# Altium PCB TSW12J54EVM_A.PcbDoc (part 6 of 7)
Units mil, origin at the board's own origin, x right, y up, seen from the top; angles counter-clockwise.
Board outline 6301 x 2680 mil, 10 copper layers (Top Layer - L1, Gnd-Plane - L2, Signals - L3, Gnd-Plane - L4, Pwr Plane - L5, Signals - L6, Gnd-Plane - L7, Signals - L8, Gnd-Plane - L9, Bottom Layer - L10), stack 57.8 mil thick; 650 components, 374 nets, 2074 pads, 1402 vias.
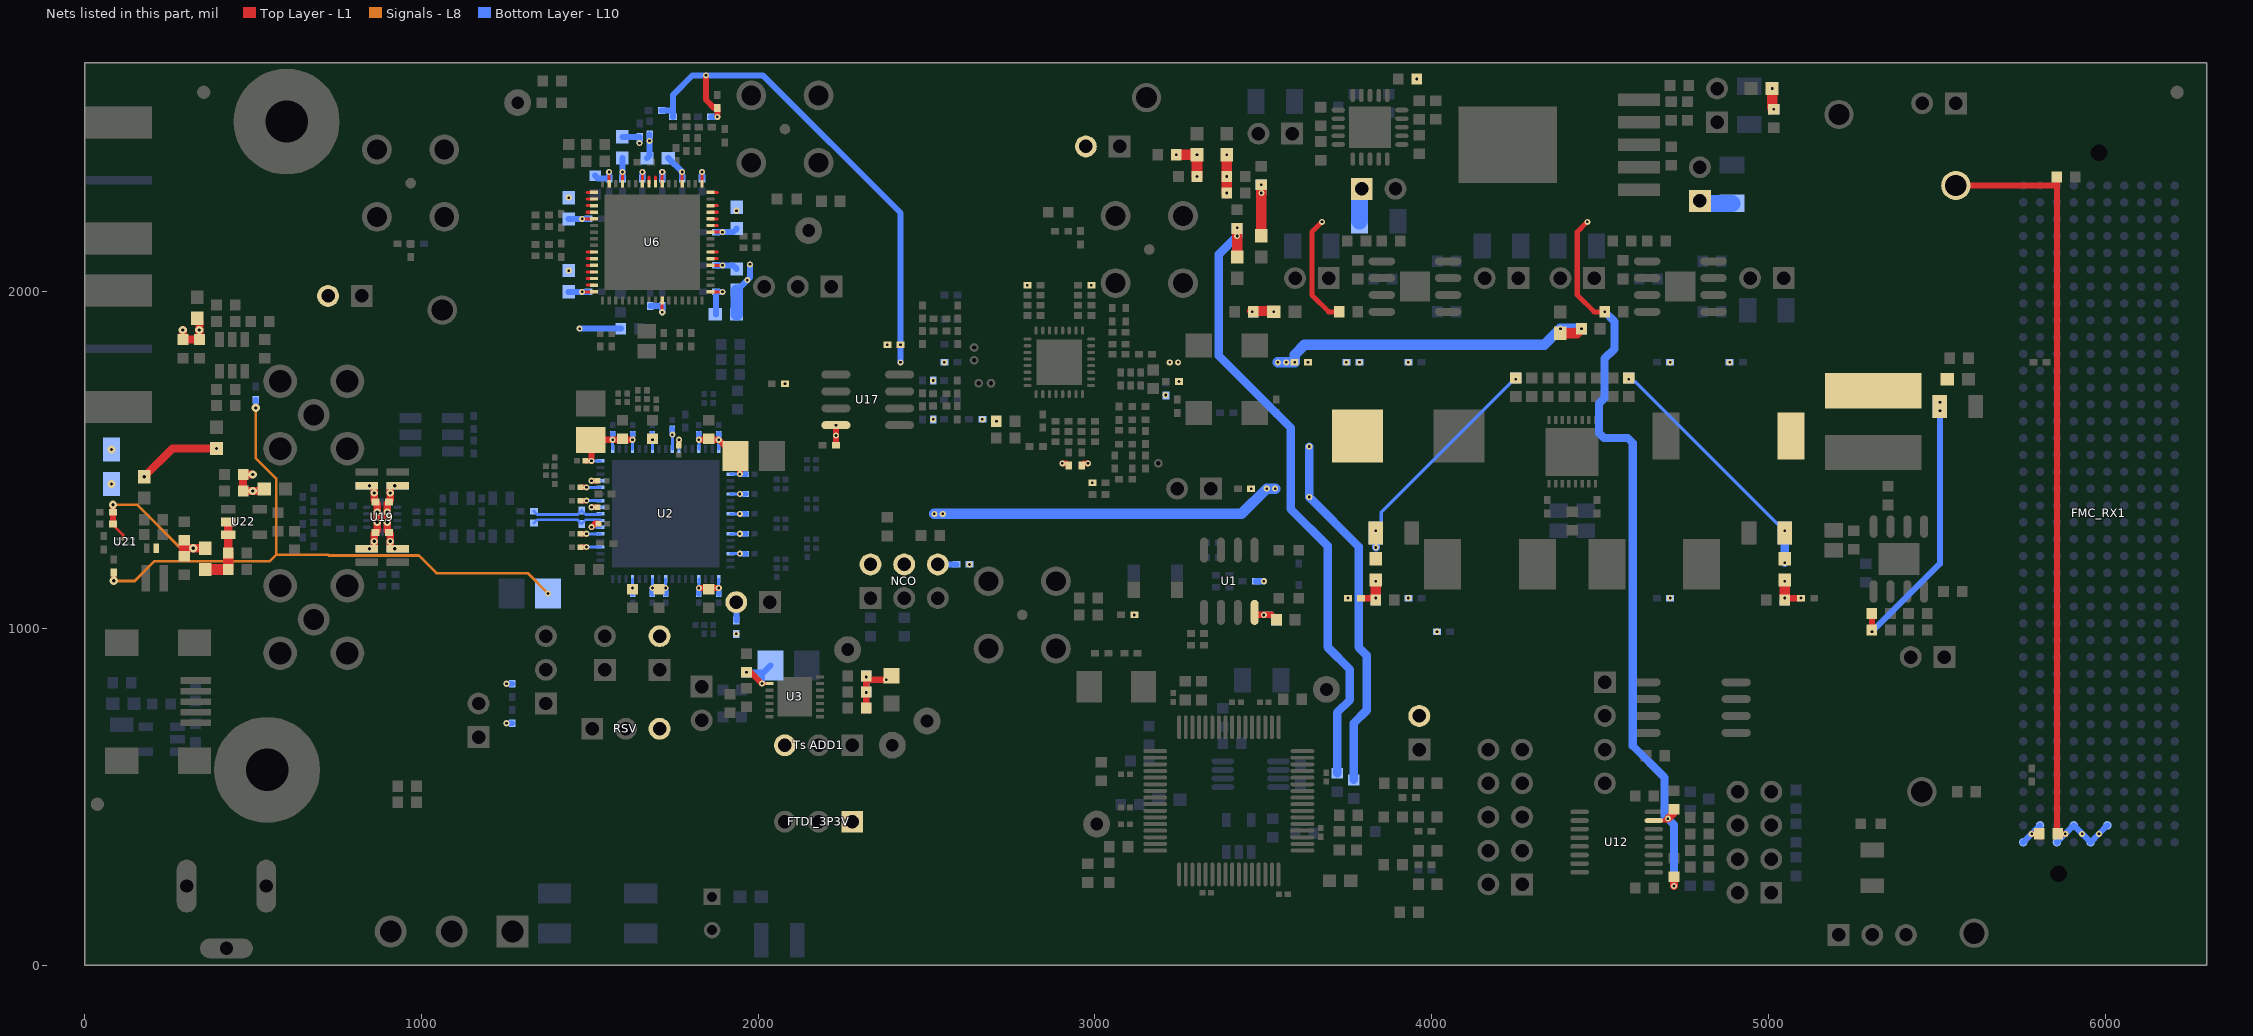
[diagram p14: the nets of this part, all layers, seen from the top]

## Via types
v1: diameter 18, hole 8, Top Layer - L1 to Bottom Layer - L10, tented both sides, 1120 vias
v2: diameter 19.68, hole 7.87, Top Layer - L1 to Bottom Layer - L10, 99 vias
v3: diameter 18, hole 8, Top Layer - L1 to Bottom Layer - L10, tented bottom, 42 vias
v4: diameter 18, hole 8, Top Layer - L1 to Bottom Layer - L10, tented top, 36 vias
v5: diameter 25, hole 10, Top Layer - L1 to Bottom Layer - L10, tented both sides, 32 vias
v6: diameter 21.46, hole 10, Top Layer - L1 to Bottom Layer - L10, tented both sides, 26 vias
v7: diameter 18, hole 8.01, Top Layer - L1 to Bottom Layer - L10, tented both sides, 16 vias
v8: diameter 18, hole 8.01, Top Layer - L1 to Bottom Layer - L10, tented bottom, 16 vias
v9: diameter 25.98, hole 12.99, Top Layer - L1 to Bottom Layer - L10, tented top, 8 vias
v10: diameter 19.68, hole 7.87, Top Layer - L1 to Bottom Layer - L10, tented top, 5 vias
v11: diameter 126, hole 106, Top Layer - L1 to Bottom Layer - L10, tented top, 2 vias

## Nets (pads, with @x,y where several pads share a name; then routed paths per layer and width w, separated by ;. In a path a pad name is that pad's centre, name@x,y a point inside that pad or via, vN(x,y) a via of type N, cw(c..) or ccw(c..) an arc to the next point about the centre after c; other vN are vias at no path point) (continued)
U6-22: U6.22 | length 20.5
  Top Layer - L1 w9: U6.22@1858.79,2097.79 1879.29,2097.79
U6-23: U6.23 | length 20.5
  Top Layer - L1 w9: U6.23@1858.79,2117.47 1879.29,2117.47
U6-27: U6.27 | length 20.5
  Top Layer - L1 w9: U6.27@1858.79,2196.21 1879.29,2196.21
U6-28: U6.28 | length 20.5
  Top Layer - L1 w9: U6.28@1858.79,2215.9 1879.29,2215.9
U6-29: U6.29 | length 20.5
  Top Layer - L1 w9: U6.29@1858.79,2235.58 1879.29,2235.58
U6-30: U6.30 | length 20.5
  Top Layer - L1 w9: U6.30@1858.79,2255.27 1879.29,2255.27
U6-32: U6.32 | length 20.5
  Top Layer - L1 w9: U6.32@1858.79,2294.64 1879.29,2294.64
U6-40: U6.40 | length 20.5
  Top Layer - L1 w9: U6.40@1695.4,2320.23 1695.4,2340.73
U6-41: U6.41 | length 20.5
  Top Layer - L1 w9: U6.41@1675.72,2320.23 1675.72,2340.73
U6-49: U6.49 | length 20.5
  Top Layer - L1 w9: 1491.83,2294.64 U6.49@1512.33,2294.64
U6-50: U6.50 | length 20.5
  Top Layer - L1 w9: 1491.83,2274.95 U6.50@1512.33,2274.95
U6-51: U6.51 | length 20.5
  Top Layer - L1 w9: 1491.83,2255.27 U6.51@1512.33,2255.27
U6-52: U6.52 | length 20.5
  Top Layer - L1 w9: 1491.83,2235.58 U6.52@1512.33,2235.58
U6-58: U6.58 | length 20.5
  Top Layer - L1 w9: 1491.83,2117.47 U6.58@1512.33,2117.47
U6-59: U6.59 | length 20.5
  Top Layer - L1 w9: 1491.83,2097.79 U6.59@1512.33,2097.79
U6-60: U6.60 | length 20.5
  Top Layer - L1 w9: 1491.83,2078.1 U6.60@1512.33,2078.1
U6-61: U6.61 | length 20.5
  Top Layer - L1 w9: 1491.83,2058.42 U6.61@1512.33,2058.42
U6-62: U6.62 | length 20.5
  Top Layer - L1 w9: 1491.83,2038.73 U6.62@1512.33,2038.73
U6-63: U6.63 | length 20.5
  Top Layer - L1 w9: 1491.83,2019.05 U6.63@1512.33,2019.05
VADJ_RX: FMC_RX1.E39 FMC_RX1.F40 FMC_RX1.G39 FMC_RX1.H40 RR6.2 RR7.1 VADJ_RX.1 | length 2487.1
  Top Layer - L1 w18: VADJ_RX.1@5556,2315 5856,2315 ; RR6.2@5856,2340 5856,2315 ; v1(5881,390) 5856,390 5856,2315
  Bottom Layer - L10 w18: FMC_RX1.H40@5856,365 v1(5881,390) FMC_RX1.G39@5906,415 v3(5931,390) FMC_RX1.F40@5956,365 v3(5981,390) FMC_RX1.E39@6006,415
VCC2: C103.1 L2.2 U6.17 | length 120.8
  Top Layer - L1 w9: U6.17@1858.79,1999.36 v1(1893.87,1999.36)
  Bottom Layer - L10 w18: L2.2@1875,1932.5 C103.1@1875,1999.36 v1(1893.87,1999.36)
VCC3: C106.1 L4.2 U6.21 | length 100.4
  Top Layer - L1 w9: U6.21@1858.79,2078.1 v1(1893.87,2078.1)
  Bottom Layer - L10 w18: C106.1@1875,2078.1 v1(1893.87,2078.1) 1925.23,2078.1 L4.2@1935.92,2067.42
VCC4: C111.1 L19.2 U6.26 | length 100.4
  Top Layer - L1 w9: U6.26@1858.79,2176.53 v1(1893.87,2176.53)
  Bottom Layer - L10 w18: C111.1@1875,2176.53 v1(1893.87,2176.53) 1925.23,2176.53 L19.2@1935.92,2187.21
VCC6: C105.1 L3.2 U6.36 | length 112.2
  Top Layer - L1 w9: U6.36@1774.14,2320.23 v1(1774.14,2355.31)
  Bottom Layer - L10 w18: L3.2@1732.95,2396.5 v1(1774.14,2355.31) C105.1@1774.14,2336.45
VCC9: C110.1 L5.2 U6.45 | length 95.1
  Top Layer - L1 w9: U6.45@1596.98,2320.23 v1(1596.98,2355.31)
  Bottom Layer - L10 w18: C110.1@1596.98,2336.45 v1(1596.98,2355.31) L5.2@1596.98,2396.5
VCC11: C120.1 L21.2 U6.53 | length 93.7
  Top Layer - L1 w9: v1(1477.24,2215.9) U6.53@1512.33,2215.9
  Bottom Layer - L10 w18: L21.2@1437.5,2215.9 v1(1477.24,2215.9) C120.1@1496.11,2215.9
VCC12: C121.1 L22.2 U6.64 | length 93.7
  Top Layer - L1 w9: v1(1477.24,1999.36) U6.64@1512.33,1999.36
  Bottom Layer - L10 w18: L22.2@1437.5,1999.36 v1(1477.24,1999.36) C121.1@1496.11,1999.36
VIN_N: R180.2 R181.1 U2.9 | length 212.5
  Bottom Layer - L10 w8: R180.2@1334.32,1347.47 1343.63,1338.16 1464.31,1338.16 R181.1@1476,1349.84 1487.68,1338.16 1530.63,1338.16 U2.9@1532.47,1340
VIN_P: R179.2 R181.2 U2.8 | length 212.5
  Bottom Layer - L10 w8: R179.2@1334.32,1312.84 1343.63,1322.16 1464.32,1322.16 R181.2@1476,1310.47 1487.69,1322.16 1530.63,1322.16 U2.8@1532.47,1320.31
VIO_1P2VA: C39.1 C40.1 C41.2 C42.2 C43.2 C44.2 C45.2 C46.2 C47.2 C48.1 C177.1 C188.1 L15.2 U2.6 U2.11 U2.14 U2.17 U2.18 U2.21 U2.65 VA12.2 | length 654.1
  Top Layer - L1 w16: C41.2@1472.64,1280.94 v1(1490.26,1280.94) ; C42.2@1472.64,1379.37 v1(1490.26,1379.37) ; C44.2@1487.64,1497.48 v1(1505.26,1497.48) ; v1(1505.26,1438.43) C43.2@1522.88,1438.43
  Top Layer - L1 w18: v1(1505.26,1497.48) 1505.26,1560.13 v1(1567.91,1560.13) v1(1626.96,1560.13)
  Top Layer - L1 w31.5: v1(3241.56,2406.01) v1(3303,2406.01) v1(3303,2341.5)
  Bottom Layer - L10 w9: v1(1490.26,1280.94) U2.6@1532.47,1280.94 ; v1(1490.26,1379.37) U2.11@1532.47,1379.37 ; v1(1505.26,1438.43) U2.14@1532.47,1438.43 ; v1(1505.26,1497.48) U2.17@1532.47,1497.48 ; U2.18@1567.91,1532.91 v1(1567.91,1560.13) ; v1(1626.96,1119.87) U2.65@1626.96,1147.09 ; U2.21@1626.96,1532.91 v1(1626.96,1560.13)
  Bottom Layer - L10 w16: v1(1567.91,1560.13) C45.2@1567.91,1577.75 ; C47.2@1626.96,1102.25 v1(1626.96,1119.87) ; v1(1626.96,1560.13) C46.2@1626.96,1577.75
VIO_1P2VD: C60.1 C61.1 C62.2 C63.2 C64.2 C65.2 C66.2 C67.2 C68.2 C69.2 C70.2 C71.2 C72.1 C95.2 C96.2 C189.1 C197.1 L16.2 NCO.2 NCO.4 NCO.6 RSV.3 U2.28 U2.31 U2.34 U2.37 U2.40 U2.43 U2.46 U2.49 U2.52 U2.55 VD12.2 | length 917.5
  Top Layer - L1 w16: C71.2@1764.76,1542.5 v1(1764.76,1560.13)
  Top Layer - L1 w18: v1(1823.81,1119.87) v1(1882.87,1119.87) ; v1(1823.81,1560.13) v1(1882.87,1560.13) 1930.25,1512.74 1930.25,1511.4 1945.51,1496.14 v1(1945.51,1458.11)
  Top Layer - L1 w31.5: v1(3391,2292.5) v1(3391,2406.01)
  Bottom Layer - L10 w9: U2.28@1764.76,1532.91 v1(1764.76,1560.13) ; v1(1823.81,1119.87) U2.55@1823.81,1147.09 ; U2.31@1823.81,1532.91 v1(1823.81,1560.13) ; v1(1882.87,1119.87) U2.52@1882.87,1147.09 ; U2.34@1882.87,1532.91 v1(1882.87,1560.13) ; U2.49@1918.3,1221.89 v1(1945.51,1221.89) ; U2.46@1918.3,1280.94 v1(1945.51,1280.94) ; U2.43@1918.3,1340 v1(1945.51,1340) ; U2.40@1918.3,1399.06 v1(1945.51,1399.06) ; U2.37@1918.3,1458.11 v1(1945.51,1458.11)
  Bottom Layer - L10 w16: C62.2@1823.81,1102.25 v1(1823.81,1119.87) ; v1(1823.81,1560.13) C70.2@1823.81,1577.75 ; C63.2@1882.87,1102.25 v1(1882.87,1119.87) ; v1(1882.87,1560.13) C69.2@1882.87,1577.75 ; v1(1945.51,1221.89) C64.2@1963.13,1221.89 ; v1(1945.51,1280.94) C65.2@1963.13,1280.95 ; v1(1945.51,1340) C66.2@1963.13,1340 ; v1(1945.51,1399.06) C67.2@1963.13,1399.05 ; v1(1945.51,1458.11) C68.2@1963.13,1458.11
  Bottom Layer - L10 w18: C96.2@1935,1023.19 VD12.2@1935,1078 ; NCO.6@2533.5,1190 C95.2@2588.31,1190
  other v1: 3391,2341.5
VIO_1P4: 1V2ADC_INT.1 C176.1 C190.1 C219.1 C221.1 C224.1 C225.1 L14.2 R83.1 | length 253.7
  Top Layer - L1 w19.5: C219.1@3790.53,1090 v1(3833.85,1090)
  Top Layer - L1 w31.5: v1(3833.85,1090) L14.2@3833.85,1143.5
  Bottom Layer - L10 w24: C190.1@3833.85,1084 v1@3833.85,1143.5
  Bottom Layer - L10 w51: R83.1@3785.18,2210.56 3785.18,2297.91 1V2ADC_INT.1@3792.27,2305
  other v1: 3930.31,1090 3833.85,1140 3785.68,1790 3930.31,1790
VIO_1P4V: C175.1 C182.1 C183.1 L12.2 L14.1 R82.2 | length 675.5
  Bottom Layer - L10 w10: C183.1@3833.85,1283 3850,1299.15 3850,1344.56 R82.2@4249,1743.56
  Bottom Layer - L10 w24: v1@3833.85,1240 C183.1@3833.85,1283
  other v1: 3833.85,1240 3833.85,1290 4249,1740
VIO_1P9V: C49.1 C50.1 C51.2 C52.2 C53.2 C54.2 C55.2 C56.2 C57.2 C58.2 C59.1 C130.1 C191.1 C202.1 L18.2 R39.1 R71.1 R80.1 R123.2 R170.1 R173.1 U2.4 U2.7 U2.10 U2.13 U2.24 U2.27 U2.60 U2.62 U12.15 VA19.2 | length 4980.1
  Top Layer - L1 w13: U12.15@4659.24,429.5 4695.5,429.5 v1(4701,435)
  Top Layer - L1 w15: v1(3674,2207) 3644,2177 3644,1990 3694,1940 R39.1@3725.44,1940 ; v1(4462,2207) 4432,2177 4432,1990 4482,1940 v1(4513.44,1940)
  Top Layer - L1 w16: v5(86.73,1140.99) R173.1@86.73,1165.3 ; C51.2@1472.64,1241.57 v1(1490.26,1241.57) ; C54.2@1472.64,1418.74 v1(1490.26,1418.74) ; v1(1505.26,1359.68) C53.2@1522.88,1359.68
  Top Layer - L1 w18: v1(1505.26,1300.63) 1515.58,1310.95 C52.2@1525.57,1310.95
  Top Layer - L1 w24: v1(4701,435) 4719,453 C130.1@4719,462.75 ; v1(4719,235.22) R123.2@4719,262.97
  Top Layer - L1 w31.5: v1(5010.5,2602.93) 5010.5,2546.49 v1(5015.5,2541.49)
  Signals - L8 w8: v5@98.73,1140.99 148.99,1140.99 207.5,1199.5 550.22,1199.5 569,1218.28 ; v5(507.99,1654.53) 508.02,1505.98 569,1445 569,1218.28 ; v1(1376,1103.87) 1315.87,1164 1045,1164 992.48,1216.52 724.48,1216.52 722.72,1218.28 569,1218.28
  Bottom Layer - L10 w9: v1(1490.26,1241.57) U2.4@1532.47,1241.57 ; v1(1490.26,1418.74) U2.13@1532.47,1418.74 ; v1(1505.26,1300.63) U2.7@1532.47,1300.63 ; v1(1505.26,1359.68) U2.10@1532.47,1359.68 ; v1(1686.02,1119.87) U2.62@1686.02,1147.09 ; U2.24@1686.02,1532.91 v1(1686.02,1560.13) ; v1(1725.39,1119.87) U2.60@1725.39,1147.09 ; U2.27@1745.07,1532.91 v1(1745.07,1575.13)
  Bottom Layer - L10 w16: v5(507.99,1654.53) R170.1@508.02,1678.84 ; C58.2@1686.01,1102.25 v1(1686.02,1119.87) ; v1(1686.02,1560.13) C55.2@1686.02,1577.75 ; C57.2@1725.39,1102.25 v1(1725.39,1119.87) ; v1(1745.07,1575.13) C56.2@1745.07,1592.75
  Bottom Layer - L10 w24: v1(4513.44,1940) 4542,1911.44 4542,1830 4513,1801 4513,1683.97 4496.61,1667.58 4496.61,1579.64 4511.25,1565 4581.97,1565 4596.61,1550.36 4596.61,651.39 4691,557 4691,445 v1(4701,435) 4719,417 v1(4719,235.22)
  other v1: 3955.22,2631
VIO_2P25: 1V9INT.1 C199.1 C203.1 C222.1 C223.1 C226.1 C227.1 L20.2 R95.1 | length 258.5
  Top Layer - L1 w19.5: v1(5048.15,1090) v1(5096.31,1090)
  Top Layer - L1 w31.5: v1(5048.15,1090) L20.2@5048.15,1143.5
  Bottom Layer - L10 w24: C203.1@5048.15,1084 v1@5048.15,1143.5
  Bottom Layer - L10 w51: 1V9INT.1@4796,2269.07 4803.09,2261.98 R95.1@4890.44,2261.98
  other v1: 4707.69,1090 5048.15,1140 4707.69,1790 4884.32,1790
VIO_2P25V: C174.2 C180.1 C181.1 L11.1 L20.1 R81.1 | length 745.3
  Bottom Layer - L10 w10: R81.1@4585,1743.56 4595.56,1733 4604,1733 5032,1305 5032,1299.15 C181.1@5048.15,1283
  Bottom Layer - L10 w24: v1@5048.15,1195 C181.1@5048.15,1283
  other v1: 5048.15,1195 5048.15,1290 4585,1740
VIO_3P3V: "Ts ADD1.3" C24.1 C25.1 C27.1 C95.1 C96.1 C115.1 C125.1 C153.1 C163.1 C215.1 C216.1 C217.1 C218.1 C219.2 C220.1 C224.2 FTDI_3P3V.1 J3.2 L9.2 R1.2 R14.2 R15.2 R16.2 R31.2 R32.2 TEMP.1 U1.8 U3.2 | length 651.2
  Top Layer - L1 w9: v1(2011.28,836.13) U3.2@2033.47,836.13
  Top Layer - L1 w18: v1(1965.28,869.44) 1977.96,869.44 v1(2011.28,836.13) ; R16.2@2320.84,763.41 v1(2320.84,809.41) 2320.84,847.47 v1(2380.28,847.47)
  Top Layer - L1 w19.5: U1.8@3474,1040 3524.93,1040 C125.1@3538.93,1026
  Top Layer - L1 w30: C153.1@3467,1942.56 3528.45,1942.56 v1(3531.01,1940)
  Bottom Layer - L10 w18: v1(1965.28,869.44) 2016.17,869.44 C27.1@2036.14,889.42 ; v1(2011.28,836.13) C27.1@2011.3,869.44 ; v1(2320.84,809.41) v1(2320.84,855.81) ; v1(3467,1940) v1(3531.01,1940) ; R1.2@3477.69,1140 v1(3501.5,1140)
  Bottom Layer - L10 w19.5: v1(3501.5,1040) 3524.93,1040 C115.1@3538.93,1026
  other v1: 1935,983.82 4015.31,990 3116.68,1040 3751.16,1090 2627.68,1190 2079.68,1726 3632.24,1790 3746.31,1790 2383.32,1842
VIO_3P3V_LMK_CLK: C116.1 C171.1 L2.1 L4.1 L13.2 L19.1 L21.1 L22.1 R47.2 R131.1 | length 2191.3
  Top Layer - L1 w31.5: L13.2@3422,2102.99 C116.1@3422,2187.44
  Bottom Layer - L10 w18: v1(1470,1890) R47.2@1592.23,1890 ; L4.1@1935.92,2001.92 v1(1968,2034) 1976,2042 v1(1976,2081)
  Bottom Layer - L10 w25: v1(3422,2165) 3368,2111 3368,1809 3581,1596 3581,1355 3691,1245 3691,944 3757,878 3757,788 3719,750 R131.1@3719,569.71
  Bottom Layer - L10 w31.5: v1@3422,2162.44 C171.1@3422,2187.44
  Bottom Layer - L10 w37.5: L2.1@1935.92,1932.5 L4.1@1935.92,2001.92
  other v1: 1437.5,2062.35 3422,2190 1935.92,2240 1437.5,2278.89
VIO_3P3V_LMK_PLL: C102.1 C104.1 C107.1 C108.1 C109.1 C164.1 C165.1 C206.1 C207.1 C208.1 C209.1 L3.1 L5.1 L10.2 U6.10 U6.33 U6.39 U6.42 U6.47 | length 669.2
  Top Layer - L1 w9: U6.47@1557.61,2320.23 v1(1557.61,2355.31) ; U6.42@1656.03,2320.23 v1(1656.03,2355.31) ; v1(1715.09,1938.69) U6.10@1715.09,1973.77 ; U6.39@1715.09,2320.23 v1(1715.09,2355.31) ; U6.33@1833.2,2320.23 v1(1833.2,2355.31)
  Top Layer - L1 w31.5: L10.2@3494,2165.99 v1(3494,2317.5)
  Bottom Layer - L10 w18: C108.1@1515.92,2344.32 1523.79,2336.44 C209.1@1557.61,2336.45 v1(1557.61,2355.31) ; L5.1@1596.98,2459.5 C107.1@1647.92,2459.5 v1(1647.92,2440.63) ; C208.1@1656.03,2336.45 v1(1656.03,2355.31) ; L3.1@1669.96,2396.5 1677.05,2403.59 v1(1677.05,2447.5) C104.1@1677.05,2466.37 ; C109.1@1679.72,1957.55 C102.1@1715.09,1957.55 v1(1715.09,1938.69) ; C207.1@1715.09,2336.45 v1(1715.09,2355.31) ; C206.1@1833.2,2336.45 v1(1833.2,2355.31)
  Bottom Layer - L10 w31.5: v1(3494,2292.5) v1(3494,2317.5)
VIO_3P3V_LMX: C144.1 C152.1 C216.2 C217.2 C258.2 C259.2 C260.2 L1.1 L6.2 L27.1 L28.1 L29.1 L30.1 L31.1 L32.1 L33.1 L34.1 R130.1 R146.1 R151.1 R156.2 R157.2 R163.2 R164.2 U17.8 | length 3776.2
  Top Layer - L1 w18: v1(1845,2642) 1845,2569.78 1869.91,2544.87 C259.2@1878.91,2544.87 v1(1878.91,2519) ; C258.2@2230.84,1544.09 v1(2230.84,1603.5) ; v1(2903.08,1490) 2914.92,1490 L30.1@2921.92,1483 ; L29.1@2960.55,1483 2967.55,1490 v1(2979.39,1490)
  Top Layer - L1 w31.5: L6.2@4382,1876.5 4430.94,1876.5 v1(4444.44,1890)
  Bottom Layer - L10 w18: C260.2@1713.69,2537.87 1747.3,2537.87 ; R157.2@1747.3,2519 1747.3,2537.87 ; R156.2@1860.04,2519 v1(1878.91,2519) ; v1(2422.69,1790) 2422.69,2233.31 2014,2642 1805,2642 1747.3,2584.3 1747.3,2537.87
  Bottom Layer - L10 w25: v1(3636.2,1540) v1(3636.2,1390) 3783,1243.2 3783,944 3807,920 3807,757 3768,718 R130.1@3768,550.02
  Bottom Layer - L10 w31.5: v1(3542.87,1790) v1(3592.87,1790) 3592.87,1812.87 3622,1842 4334,1842 v1(4382,1890) v1(4444.44,1890)
  other v1: 3463.69,1415 2992.31,1432.5 2230.84,1572.81 2707.44,1615 2519.36,1620.81 2665.69,1620.82 3210,1692.98 3249.52,1733.13 2519.36,1736.19 2552.68,1790 3221.92,1790 3246.92,1790 3567.87,1790 2422.69,1842 2799.35,2019.09 2989.12,2019.09
VIO_3P75: "LMH PD.2" C265.1 C267.2 C269.2 C271.1 C273.1 C274.1 C275.1 C280.1 C281.1 L43.2 R183.1 U19.1 U19.10 | length 638.3
  Top Layer - L1 w19.68: C265.1@907.26,1237.02 C265.1@930.03,1237.02 ; C271.1@907.26,1423.29 C271.1@930.03,1423.29
  Top Layer - L1 w21.46: C265.1@907.26,1237.02 v6(907.26,1258.4) 907.26,1280.91 898.34,1289.83 v6(898.34,1315.42) v6(898.34,1344.89) 898.34,1370.48 907.26,1379.4 v6(907.26,1401.91) C271.1@907.26,1423.29
  Top Layer - L1 w24: v5(291.99,1886.02) C280.1@291.99,1857.77 C281.1@340.99,1857.77 v5(340.99,1886.02) 340.99,1914.51 L43.2@335,1920.5
  Bottom Layer - L10 w9.84: v6(898.34,1315.42) 903.3,1310.74 903.3,1262.37 v6(907.26,1258.4) ; v6(898.34,1344.89) 903.3,1349.57 U19.10@903.3,1375.43 903.3,1397.94 v6(907.26,1401.91)
  Bottom Layer - L10 w16: v1(1252.51,718.32) R183.1@1269.78,718.32
  Bottom Layer - L10 w19.68: C267.2@907.26,1237.02 C267.2@930.03,1237.02 ; C269.2@907.26,1423.29 C269.2@930.03,1423.29
  Bottom Layer - L10 w21.46: v6(898.34,1315.42) v6(898.34,1344.89) ; C267.2@907.26,1237.02 v6(907.26,1258.4) ; v6(907.26,1401.91) C269.2@907.26,1423.29
  other v5: 80,1531.12
  other v6: 921.26,1236.94 921.26,1423.38
VIO_4P05V: C154.2 C156.2 C157.2 L7.1 L8.2 L35.1 L36.1 R72.1 | length 2081.1
  Top Layer - L1 w18: R72.1@5306.88,995 C154.2@5306.88,1044
  Top Layer - L1 w24: v5(177.17,1450.49) 260.71,1534.03 v5(391.73,1534.03)
  Bottom Layer - L10 w18: v1(5306.88,990) 5508.85,1191.97 v1(5508.85,1646.25)
  Bottom Layer - L10 w31.5: v1(2523,1340) v1(2548,1340) 3435,1340 v1(3510,1415) v1(3535,1415)
  other v1: 5508.85,1671.25
VIO_-1P25: C264.2 C266.1 C268.1 C270.2 C273.2 C274.2 C275.2 C289.1 C290.1 L44.2 R182.1 U19.3 U19.8 | length 638.3
  Top Layer - L1 w19.68: C264.2@837.19,1237.02 C264.2@859.96,1237.02 ; C270.2@837.19,1423.29 C270.2@859.96,1423.29
  Top Layer - L1 w21.46: C264.2@859.96,1237.02 v6(859.96,1258.4) 859.96,1280.91 C273.2@863.93,1284.88 868.88,1289.83 v6(868.88,1315.42) v6(868.88,1344.89) 868.88,1370.48 C274.2@863.93,1375.43 859.96,1379.4 v6(859.96,1401.91) C270.2@859.96,1423.29
  Top Layer - L1 w24: v5(498.81,1457) C290.1@470.56,1457 C289.1@470.56,1408 v5(498.81,1408) 527.3,1408 L44.2@533.3,1413.99
  Bottom Layer - L10 w9.84: v6(859.96,1258.4) 863.93,1262.37 U19.3@863.93,1284.88 863.93,1310.74 v6(868.88,1315.42) ; v6(859.96,1401.91) 863.93,1397.94 U19.8@863.93,1375.43 863.93,1349.57 v6(868.88,1344.89)
  Bottom Layer - L10 w16: v1(1252.51,835.69) R182.1@1269.78,835.68
  Bottom Layer - L10 w19.68: C266.1@837.19,1237.02 C266.1@859.96,1237.02 ; C268.1@837.19,1423.29 C268.1@859.96,1423.29
  Bottom Layer - L10 w21.46: C266.1@859.96,1237.02 v6(859.96,1258.4) ; v6(859.96,1401.91) C268.1@859.96,1423.29 ; v6(868.88,1315.42) v6(868.88,1344.89)
  other v5: 80,1428.76
  other v6: 845.96,1236.94 845.96,1423.38
VIO_-3P25: C287.1 C288.1 L42.2 U22.2 U22.3 | length 209.1
  Top Layer - L1 w25: C288.1@426.07,1224 U22.3@426.07,1278.6 U22.2@426.07,1316
  Top Layer - L1 w31.5: L42.2@358,1175 C287.1@426.07,1175 C288.1@426.07,1224
VIO_-3P25V: C284.2 C285.2 C286.1 D1.2 L42.1 R174.2 U21.B2 | length 515
  Top Layer - L1 w8: R174.2@84.42,1309.99 84.42,1307.3 113.86,1277.86 U21.B2@113.86,1265.86
  Top Layer - L1 w19: R174.2@84.42,1309.99 C286.1@84.42,1344.99 v5(84.42,1367.33)
  Top Layer - L1 w25: 295.73,1237.99 v5(323,1237.99) L42.1@358,1237.99
  Top Layer - L1 w31.5: C284.2@295.73,1214.55 295.73,1237.99 C285.2@295.73,1261.43
  Signals - L8 w8: v5@96.42,1367.33 155.95,1367.33 285.29,1237.99 v5@335,1237.99
VIO_B_M2C_RX: FMC_RX1.J39 FMC_RX1.K40 RR7.2 | length 93.2
  Top Layer - L1 w18: v1(5781,390) RR7.2@5803.44,390
  Bottom Layer - L10 w18: FMC_RX1.K40@5756,365 v1(5781,390) FMC_RX1.J39@5806,415
pads on no net: 5VDC.3 "SH-Ts ADD1_1_2.0" FID1.1 FID2.1 FID3.1 FMC_RX1.401 FMC_RX1.402 FMC_RX1.A22 FMC_RX1.A23 FMC_RX1.A26 FMC_RX1.A27 FMC_RX1.A30 FMC_RX1.A31 FMC_RX1.A34 FMC_RX1.A35 FMC_RX1.A38 FMC_RX1.A39 FMC_RX1.B1 FMC_RX1.B4 FMC_RX1.B5 FMC_RX1.B8 FMC_RX1.B9 FMC_RX1.B20 FMC_RX1.B21 FMC_RX1.B24 FMC_RX1.B25 FMC_RX1.B28 FMC_RX1.B29 FMC_RX1.B32 FMC_RX1.B33 FMC_RX1.B36 FMC_RX1.B37 FMC_RX1.B40 FMC_RX1.C2 FMC_RX1.C3 FMC_RX1.C10 FMC_RX1.C11 FMC_RX1.C14 FMC_RX1.C15 FMC_RX1.C18 FMC_RX1.C19 FMC_RX1.C22 FMC_RX1.C23 FMC_RX1.C26 FMC_RX1.C27 FMC_RX1.D8 FMC_RX1.D9 FMC_RX1.D11 FMC_RX1.D12 FMC_RX1.D14 FMC_RX1.D15 FMC_RX1.D17 FMC_RX1.D18 FMC_RX1.D20 FMC_RX1.D21 FMC_RX1.D23 FMC_RX1.D24 FMC_RX1.D27 FMC_RX1.D29 FMC_RX1.D33 FMC_RX1.D34 FMC_RX1.E2 FMC_RX1.E3 FMC_RX1.E6 FMC_RX1.E7 FMC_RX1.E9 FMC_RX1.E10 FMC_RX1.E15 FMC_RX1.E16 FMC_RX1.E18 FMC_RX1.E19 FMC_RX1.E21 FMC_RX1.E22 FMC_RX1.E24 FMC_RX1.E25 FMC_RX1.E27 FMC_RX1.E28 FMC_RX1.E30 FMC_RX1.E31 FMC_RX1.E33 FMC_RX1.E34 FMC_RX1.E37 FMC_RX1.F4 FMC_RX1.F5 FMC_RX1.F7 FMC_RX1.F8 FMC_RX1.F10 FMC_RX1.F11 FMC_RX1.F13 FMC_RX1.F14 FMC_RX1.F16 FMC_RX1.F17 FMC_RX1.F19 FMC_RX1.F20 FMC_RX1.F22 FMC_RX1.F23 FMC_RX1.F25 FMC_RX1.F26 FMC_RX1.F28 FMC_RX1.F29 FMC_RX1.F31 FMC_RX1.F32 FMC_RX1.F34 FMC_RX1.F35 FMC_RX1.F37 FMC_RX1.F38 FMC_RX1.G2 FMC_RX1.G3 FMC_RX1.G15 FMC_RX1.G16 FMC_RX1.G18 FMC_RX1.G19 FMC_RX1.G21 FMC_RX1.G22 FMC_RX1.G24 FMC_RX1.G25 FMC_RX1.G28 FMC_RX1.G31 FMC_RX1.H1 FMC_RX1.H4 FMC_RX1.H5 FMC_RX1.H7 FMC_RX1.H8 FMC_RX1.H10 FMC_RX1.H11 FMC_RX1.H13 FMC_RX1.H14 FMC_RX1.H16 FMC_RX1.H17 FMC_RX1.H19 FMC_RX1.H20 FMC_RX1.H22 FMC_RX1.H23 FMC_RX1.H25 FMC_RX1.H26 FMC_RX1.H28 FMC_RX1.H29 FMC_RX1.H32 FMC_RX1.H35 FMC_RX1.J2 FMC_RX1.J3 FMC_RX1.J6 FMC_RX1.J7 FMC_RX1.J9 FMC_RX1.J10 FMC_RX1.J12 FMC_RX1.J13 FMC_RX1.J18 FMC_RX1.J19 FMC_RX1.J21 FMC_RX1.J22 FMC_RX1.J24 FMC_RX1.J25 FMC_RX1.J27 FMC_RX1.J28 FMC_RX1.J30 FMC_RX1.J31 FMC_RX1.J33 FMC_RX1.J34 FMC_RX1.J36 FMC_RX1.J37 FMC_RX1.K1 FMC_RX1.K4 FMC_RX1.K5 FMC_RX1.K7 FMC_RX1.K8 FMC_RX1.K10 FMC_RX1.K11 FMC_RX1.K13 FMC_RX1.K14 FMC_RX1.K16 FMC_RX1.K17 FMC_RX1.K19 FMC_RX1.K20 FMC_RX1.K22 FMC_RX1.K23 FMC_RX1.K25 FMC_RX1.K26 FMC_RX1.K31 FMC_RX1.K32 FMC_RX1.K34 FMC_RX1.K35 H3.0 H4.0 H5.1 H6.1 S1.3 SH-1V2ADC_INT_1_2.0 SH-1V2ADC_LDO_1_2.0 SH-1V9ADC_1_2.0 SH-1V9INT_1_2.0 SH-5V_12V_1_2.0 SH-FTDI_3P3V_1_2.0 SH-J2_1_2.0 SH-LMK_INT_1_2.0 SH-LMK_LDO_1_2.0 SH-LMX_INT_1_2.0 SH-LMX_LDO_1_2.0 SH-RSV_1_2.0 U3.1 U3.3 U3.4 U5.2 U5.7 U8.2 U8.7 U10.2 U10.3 U10.4 U10.9 U10.13 U10.14 U10.17 U13.21 U13.22 U13.23 U13.24 U13.30 U13.32 U13.33 U13.34 U13.36 U13.44 U13.45 U13.46 U13.48 U13.52 U13.53 U13.54 U13.55 U13.57 U13.58 U13.59 U13.60 U15.6 U15.7 U16.7 U17.4 USB.4 uWIRE.1 uWIRE.3 uWIRE.5 uWIRE.7 Vcmo_2_3.0
copper on no net:
  other v11: 5902,100 5902,2580

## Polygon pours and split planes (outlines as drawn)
no net on Top Overlay "Top Overlay-No Net" (solid): 6006,139 6006,39 6106,39 6106,139 6006,139
no net on Top Overlay "Top Overlay-No Net" (solid): 6156,139 6156,39 6256,39 6256,139 6156,139
VIO_3P3V_LMK_PLL on Signals - L8 "Signals - L8-VIO_3P3V_LMK_PLL" (solid, pour order 57): 1670,1924 1730,1924 1730,1995 1765,2030 1848,2030 1848,2277 3528,2277 3528,2353 1848,2353 1848,2497 1523,2497 1523,1974 1670,1974
VIO_3P3V_LMK_CLK on Signals - L8 "Signals - L8-VIO_3P3V_LMK_CLK" (solid, pour order 63): 2083,2153 3653,2153 3653,2661 1393,2660 1393,1871 1498,1871 1498,2522 1873,2522 1873,2378 3553,2378 3553,2252 1872,2252 1872,2025 1985,2025 1985,2097 1962,2097 1962,2197 2039,2197
VIO_4P05V on Signals - L3 "Signals - L3-VIO_4P05V" (solid, pour order 78): 5531,1400 5531,1695 3492,1695 3492,1400
VIO_1P9V on Signals - L3 "Signals - L3-VIO_1P9V" (solid, pour order 55): 1459,2660 5022,2660 5022,2094 3334,2094 3334,2285 3001,2285 3001,2094 1681,2094 1681,1592 1758,1592 1758,944 1657,944 1657,1046 1331,1046 1331,1142 1459,1142
3P3V_FTDI on Signals - L3 "Signals - L3-3P3V_FTDI" (solid, pour order 62): 2146,572 2920,572 2920,970 3207,970 3207,888 3679.89,887.9 3806.9,760.89 3807,476 3715,476 3715,451 3275,451 3275,540 3587,540 3587,793 3528,793 3528,739 3275,739 3275,783 3191,783 3191,451 3102,451 3102,377 3715,377 3715,476 3807,476 3807,389 3722,304 3721.9,167.11 3634.89,80.1 3245.11,80.1 3122,203 2981.21,203 2920.1,264.11 2920.1,443 2212,443 2212,393 2146,393
1P8V_USB on Signals - L3 "Signals - L3-1P8V_USB" (solid, pour order 64): 3112,387 3112,441 3201,441 3201,773 3265,773 3265,729 3538,729 3538,783 3577,783 3577,550 3265,550 3265,441 3705,441 3705,387
VIO_3P3V_LMX on Signals - L3 "Signals - L3 - VIO_3P3V_LMX" (solid, remove dead copper, pour order 74): 3260,2043 2965,2043 2965,1954 3019,1954 3019,1777 3260,1777
VIO_3P3V_LMX on Signals - L3 "Signals - L3- VIO_3P3V_LMX" (solid, remove dead copper, pour order 73): 2410,2043 2823,2043 2823,1954 2539,1954 2539,1777 2410,1777
3P3V_USB on Signals - L3 "Signals - L3-3P3V_USB" (solid, remove dead copper, pour order 61): 20.1,1029.9 400.9,1029.9 400.9,843.1 436,808 641,808 877,572 2112,572 2112,393 2047,393 2047,443 902,443 609,736 493,736 401,644 400.9,535.1 20.1,535.1
VIO_4P05V on Signals - L3 "Signals - L3-VIO_4P05V" (solid, remove dead copper, pour order 77): 1783,1355 1783,919 1632,919 1632,1021 1306,1021 1306,1477 856,1477 856,1595 20,1595 20,1055 426,1055 426,854 447,833 652,833 888,597 2566,597 2566,1355
GND on Bottom Layer - L10 "Bottom Layer - L10-T2-GND" (solid, pour order 53): 867,1489 1045,1489 1045,1560 1126,1560 1126,1590 1045,1590 1045,1661 867,1661
GND on Bottom Layer - L10 "Bottom Layer - L10-U10-GND" (solid, pour order 52): 3753,2426 3889,2426 3889,2550 3753,2550 3738,2565 3706,2565 3706,2530 3753,2483
GND on Bottom Layer - L10 "Bottom Layer - L10-U6-GND" (solid, pour order 54): 1523,1989 1574,1989 1574,1978 1608,1978 1608,1985 1848,1985 1848,2310 1547,2310 1547,2305 1499,2305 1499,2273 1523,2273
5P0_12P0V_INT on Bottom Layer - L10 "Top Layer L10-12P0_INT" (solid, pour order 44): 4452,1405 4382,1405 4382,1327 4452,1327 4452,1405
GND on Bottom Layer - L10 "Top Layer L10-GND" (solid, pour order 68): 2448,2000 2448,1834 2565,1834 2565,2000
GND on Bottom Layer - L10 "Top Layer L10-GND" (solid, pour order 67): 2825.34,1858.9 2825.34,1721.1 2963.13,1721.1 2963.13,1858.9
GND on Bottom Layer - L10 "Bottom Layer - L10 - Anolog In GND" (solid, remove dead copper, pour order 47): 20.1,1594.9 20.1,1040.1 412,1040 412,847 440.11,818.1 646,818 1277,818 1277,1183.32 1371,1277 1482,1277 1482,1383 1371,1383 1277,1477 844,1477 844,1787 279,1787 279,1595
NetD1_1 on Top Layer - L1 "Top Layer - L1-NetD1_1" (solid, pour order 45): 140,1103 140,1255 194,1255 194,1103
GND on Top Layer - L1 "Top Layer L1-U7-GND" (solid, pour order 65): 5637,1158 5637,1694 5593,1694 5593,1614 5472,1614 5472,1336 5450,1336 5450,1254 5166,1254 5166,1158 5558,1158 5558,1092 5591,1092 5591,1158
VIO_2P25V on Top Layer - L1 "Top Layer L1- VIO_1P4V" (solid, pour order 75): 5027,1650 5106,1650 5106,1186 5027,1186 5027,1650
VIO_1P4V on Top Layer - L1 "Top Layer L1- VIO_1P4V" (solid, pour order 76): 3855,1650 3703,1650 3703,1186 3855,1186 3855,1650
NetC169_2 on Top Layer - L1 "Top Layer L1-NetC169_2" (solid, pour order 71): 4461,1442 4472,1442 4472,1405 4476,1405 4476,1353 4656,1353 4656,1650 4830,1650 4830,1276 4576,1276 4576,1115 4461,1115
NetC170_1 on Top Layer - L1 "Top Layer L1-NetC170_1" (solid, pour order 72): 4373,1442 4362,1442 4362,1405 4358,1405 4358,1353 4178,1353 4178,1650 4004,1650 4004,1276 4258,1276 4258,1115 4373,1115
NetC168_1 on Top Layer - L1 "Top Layer L1-NetC168_1" (solid, pour order 43): 4452,1643 4382,1643 4382,1704 4452,1704 4452,1643
GND on Top Layer - L1 "Top Layer L1-U7-SW_GND" (solid, pour order 66): 5324,1346 5324,1453 5166,1453 5166,1346
5P0_12P0V_INT on Top Layer - L1 "Top Layer L1-U7-12V_int" (solid, pour order 69): 5324,1269 5324,1336 5166,1336 5166,1269
VIO_4P05V on Top Layer - L1 "Top Layer L1-VIO_3P6V" (solid, pour order 70): 5531,1624 5531,1720 5550,1720 5550,1758 5167,1758 5167,1653 5472,1653 5472,1624
5P0_12P0V_INT on Top Layer - L1 "Top Layer L1-12P0_INT" (solid, pour order 51): 4452,1405 4382,1405 4382,1331 4452,1331 4452,1405
VIO_1P9V on Top Layer - L1 "Top Layer L1-VIO_1P9V" (solid, remove dead copper, pour order 60): 1535,1301 1515,1301 1515,1297 1509,1291 1502,1291 1496,1297 1496,1363 1502,1369 1532,1369 1532,1320 1535,1320
Net1V2ADC_LDO_1 on Top Layer - L1 "Top Layer L1-NetC172_1" (solid, pour order 58): 3741.68,2495 3741.68,2413 3765.68,2413 3765.68,2374 3702.68,2374 3702.68,2430 3552.68,2430 3552.68,2508 3687.68,2508 3687.68,2495
Net1V2ADC_INT_2 on Top Layer - L1 "Top Layer L1-NetC172_1" (solid, pour order 59): 3891.68,2488 3891.68,2413 3861,2413 3861,2272 3931,2272 3931,2393 3980,2393 3980,2425 3930.68,2425 3930.68,2488
GND on Top Layer - L1 "Top Layer L1-U2-GND" (solid, pour order 56): 1557,1182 1557,1303 1542,1303 1542,1368 1553,1368 1553,1430 1540,1430 1540,1447 1557,1447 1557,1526 1884,1526 1884,1182
GND on Top Layer - L1 "Top Layer L1-U9 GND" (solid, pour order 42): 4612,1819 3669,1819 3669,1111 3805,1111 3805,1177 3693,1177 3693,1660 3865,1660 3865,1111 3915,1111 3915,1032 4586,1032 4586,1105 4452,1105 4452,1307.54 4382,1307.54 4382,1105 4248,1105 4248,1266 3994,1266 3994,1660 4187,1660 4188,1363 4323,1363 4323,1453 4511,1453 4511,1363 4646,1363 4646,1660 4840,1660 4840,1266 4586,1266 4586,1032 4967,1032 4967,1110 5017,1110 5017,1660 5116,1660 5116,1176 5077,1176 5077,1110 5140,1110 5141,1782 5510,1782 5510,1819 4612,1819 4612,1663 4532,1663 4511,1642 4511,1596 4323,1596 4323,1642 4302,1663 4222,1663 4222,1769 4280,1769 4280,1728 4410,1728 4410,1769 4472,1769 4472,1728 4554,1728 4554,1769 4612,1769
VIO_-3P25V on Top Layer - L1 "Top Layer - L1-NetC284_2" (solid, pour order 49): 204.73,1251.66 312.73,1251.66 312.73,1223.66 204.73,1223.66 204.73,1251.66
NetC282_1 on Top Layer - L1 "Top Layer - L10-NetC282_1" (solid, pour order 48): 140.73,1406.99 140.73,1260.99 193.73,1260.99 193.73,1406.99
GND on Top Layer - L1 "Top Layer - L1 - Anolog In GNF" (solid, remove dead copper, pour order 50): 20.1,1594.9 20.1,1040.1 412,1040 412,856 1312,856 1312,1173 1430,1173 1430,1247 1482,1247 1482,1383 1371,1383 1277,1477 852,1477 852,2027 259,2027 259,1595
VIO_-1P25 on Signals - L6 "Signals - L6 - L10-VIO_-1P25" (solid, remove dead copper, pour order 46): 20,1595 20,1040 412,1040 412,847 440.11,818.1 646,818 881,583 1289,583 1289,1028 1012,1028 1012,1477 856,1477 856,2020 259,2020 259,1595
GND2 on Gnd-Plane - L2 (split plane): 400.9,845 401.29,843.05 402.4,841.4 434.4,809.4 436.05,808.29 438,807.9 641.52,807.9 875.65,573.77 877.31,572.66 879.26,572.27 2915,572.27 2916.95,572.66 2918.6,573.77 2919.71,575.42 2920.1,577.37 2920.1,969.9 3206.9,969.9 3206.9,893 3207.29,891.05 3208.4,889.4 3210.05,888.29 3212,887.9 3679.89,887.9 3806.9,760.89 3806.9,389.11 3723.4,305.6 3722.29,303.95 3721.9,302 3721.9,167.11 3634.89,80.1 3245.11,80.1 3123.6,201.6 3121.95,202.71 3120,203.1 2981.11,203.1 2920.1,264.11 2920.1,438 2919.71,439.95 2918.6,441.6 2916.95,442.71 2915,443.1 902.11,443.1 610.6,734.6 608.95,735.71 607,736.1 495,736.1 493.05,735.71 491.4,734.6 402.4,645.6 401.29,643.95 400.9,642 400.9,535.1 20.1,535.1 20.1,1029.9 400.9,1029.9
GND on Gnd-Plane - L2 (split plane): 6280.9,20.1 20.1,20.1 20.1,524.9 406,524.9 407.95,525.29 409.6,526.4 410.71,528.05 411.1,530 411.1,639.89 497.11,725.9 604.89,725.9 896.39,434.4 898.05,433.29 898.44,433.21 900,432.9 2909.9,432.9 2909.9,262 2910.29,260.05 2911.4,258.4 2975.4,194.4 2977.05,193.29 2979,192.9 3117.89,192.9 3239.4,71.4 3241.05,70.29 3243,69.9 3637,69.9 3638.95,70.29 3640.6,71.4 3730.6,161.4 3731.71,163.05 3732.1,165 3732.1,299.89 3815.6,383.4 3816.71,385.05 3817.1,387 3817.1,763 3816.71,764.95 3815.6,766.6 3685.6,896.6 3683.95,897.71 3682,898.1 3217.1,898.1 3217.1,975 3216.71,976.95 3215.6,978.6 3213.95,979.71 3212,980.1 2915,980.1 2913.05,979.71 2911.4,978.6 2910.29,976.95 2909.9,975 2909.9,582.47 881.37,582.47 647.23,816.6 645.58,817.71 643.63,818.1 440.11,818.1 411.1,847.11 411.1,1035 410.71,1036.95 409.6,1038.6 407.95,1039.71 406,1040.1 20.1,1040.1 20.1,2659.9 6280.9,2659.9
GND on Gnd-Plane - L4 (split plane): 6280.9,20.1 20.1,20.1 20.1,2659.9 6280.9,2659.9
NetC158_1 on Pwr Plane - L5 (split plane): 6280.9,1995.1 4909.1,1995.1 4909.1,2419 4908.71,2420.95 4907.6,2422.6 4905.95,2423.71 4904,2424.1 4688,2424.1 4686.05,2423.71 4684.4,2422.6 4683.29,2420.95 4682.9,2419 4682.9,1995.1 4212.1,1995.1 4212.1,2659.9 6280.9,2659.9
VIO_2P25 on Pwr Plane - L5 (split plane): 4898.9,1184 4899.29,1182.05 4900.4,1180.4 4902.05,1179.29 4904,1178.9 5110.9,1178.9 5110.9,1045.1 4693.1,1045.1 4693.1,2413.9 4898.9,2413.9
VIO_3P3V_LMX on Pwr Plane - L5 (split plane): 2478.9,1840 2479.29,1838.05 2480.4,1836.4 2482.05,1835.29 2484,1834.9 3607.45,1834.9 3607.45,1740 3607.84,1738.05 3608.95,1736.4 3610.6,1735.29 3612.55,1734.9 3650.45,1734.9 3650.45,1468.1 3503,1468.1 3501.05,1467.71 3499.4,1466.6 3498.29,1464.95 3497.9,1463 3497.9,1381.1 3429.1,1381.1 3429.1,1415 3428.71,1416.95 3427.6,1418.6 3425.95,1419.71 3424,1420.1 2942.11,1420.1 2845.6,1516.6 2843.95,1517.71 2842,1518.1 2282.1,1518.1 2282.1,1558 2281.71,1559.95 2280.6,1561.6 2278.95,1562.71 2277,1563.1 2222.1,1563.1 2222.1,1707.17 2403,1707.17 2404.95,1707.56 2406.6,1708.67 2407.71,1710.32 2408.1,1712.27 2408.1,1859.9 2478.9,1859.9
5P0_12P0V_INT on Pwr Plane - L5 (split plane): 4201.9,1990 4202.29,1988.05 4203.4,1986.4 4205.05,1985.29 4207,1984.9 4682.9,1984.9 4682.9,1040 4683.29,1038.05 4684.4,1036.4 4686.05,1035.29 4688,1034.9 5116,1034.9 5117.95,1035.29 5119.6,1036.4 5120.71,1038.05 5121.1,1040 5121.1,1184 5120.71,1185.95 5119.6,1187.6 5117.95,1188.71 5116,1189.1 4909.1,1189.1 4909.1,1984.9 6280.9,1984.9 6280.9,670.1 6106,670.1 6104.05,669.71 6102.4,668.6 6101.29,666.95 6100.9,665 6100.9,570.1 5358,570.1 5356.05,569.71 5354.4,568.6 5353.29,566.95 5352.9,565 5352.9,20.1 5263.1,20.1 5263.1,190 5262.71,191.95 5261.6,193.6 5259.95,194.71 5258,195.1 4040.1,195.1 4040.1,1040 4039.71,1041.95 4038.6,1043.6 4036.95,1044.71 4035,1045.1 3955.1,1045.1 3955.1,2659.9 4201.9,2659.9
12P0V_RX on Pwr Plane - L5 (split plane): 6280.9,20.1 5363.1,20.1 5363.1,559.9 6106,559.9 6107.95,560.29 6109.6,561.4 6110.71,563.05 6111.1,565 6111.1,659.9 6280.9,659.9
VIO_1P4 on Pwr Plane - L5 (split plane): 3944.9,1045.1 3771.1,1045.1 3771.1,1990 3770.71,1991.95 3769.6,1993.6 3767.95,1994.71 3766,1995.1 3538.1,1995.1 3538.1,2659.9 3944.9,2659.9
VIO_1P2VA on Pwr Plane - L5 (split plane): 3341.9,2086.1 1677.04,2086.1 1675.09,2085.71 1673.43,2084.6 1583.4,1994.57 1582.29,1992.91 1581.9,1990.96 1581.9,1844.89 1582.29,1842.94 1583.4,1841.29 1646.9,1777.78 1646.9,1040.1 1022.88,1040.1 1022.88,1483 1022.5,1484.95 1021.39,1486.6 1019.74,1487.71 1017.79,1488.1 866.1,1488.1 866.1,2025 865.71,2026.95 864.6,2028.6 862.95,2029.71 861,2030.1 254,2030.1 252.05,2029.71 250.4,2028.6 249.29,2026.95 248.9,2025 248.9,1605.1 20.1,1605.1 20.1,2659.9 3341.9,2659.9
VIO_1P2VD on Pwr Plane - L5 (split plane): 3527.9,1995.1 3433,1995.1 3431.05,1994.71 3429.4,1993.6 3428.29,1991.95 3427.9,1990 3427.9,1945.1 3014,1945.1 3012.05,1944.71 3010.4,1943.6 2986.89,1920.1 1997,1920.1 1995.05,1919.71 1993.4,1918.6 1963.4,1888.6 1962.29,1886.95 1961.9,1885 1961.9,1710 1962.29,1708.05 1963.4,1706.4 1996.9,1672.89 1996.9,1245 1997.29,1243.05 1998.4,1241.4 2000.05,1240.29 2002,1239.9 2565.9,1239.9 2565.9,1040.1 1762,1040.1 1760.05,1039.71 1758.4,1038.6 1757.29,1036.95 1756.9,1035 1756.9,657.1 1657.1,657.1 1657.1,1779.89 1656.71,1781.84 1655.6,1783.5 1592.1,1847.01 1592.1,1988.85 1679.15,2075.9 3347,2075.9 3348.95,2076.29 3350.6,2077.4 3351.71,2079.05 3352.1,2081 3352.1,2659.9 3527.9,2659.9
VIO_3P75 on Pwr Plane - L5 (split plane): 855.9,1483 856.29,1481.05 857.4,1479.4 859.05,1478.29 861,1477.9 1012.69,1477.9 1012.69,1035 1013.08,1033.05 1014.18,1031.4 1015.84,1030.29 1017.79,1029.9 1289.68,1029.9 1289.68,582.47 881.37,582.47 647.23,816.6 645.58,817.71 643.63,818.1 440.11,818.1 411.1,847.11 411.1,1035 410.71,1036.95 409.6,1038.6 407.95,1039.71 406,1040.1 20.1,1040.1 20.1,1594.9 254,1594.9 255.95,1595.29 257.6,1596.4 258.71,1598.05 259.1,1600 259.1,2019.9 855.9,2019.9
NetC194_1 on Pwr Plane - L5 (split plane): 400.9,845 401.29,843.05 402.4,841.4 434.4,809.4 436.05,808.29 438,807.9 641.52,807.9 875.65,573.77 877.31,572.66 879.26,572.27 2224.18,572.27 2224.18,376 2224.57,374.05 2225.67,372.4 2227.33,371.29 2229.28,370.9 2329.28,370.9 2331.23,371.29 2332.88,372.4 2333.99,374.05 2334.37,376 2334.37,572.27 2580,572.27 2581.95,572.66 2583.6,573.77 2584.71,575.42 2585.1,577.37 2585.1,969.9 3206.9,969.9 3206.9,893 3207.29,891.05 3208.4,889.4 3210.05,888.29 3212,887.9 3679.89,887.9 3806.9,760.89 3806.9,190 3807.29,188.05 3808.4,186.4 3810.05,185.29 3812,184.9 5252.9,184.9 5252.9,20.1 20.1,20.1 20.1,1029.9 400.9,1029.9
VIO_3P3V on Pwr Plane - L5 (split plane): 3760.9,1040 3761.29,1038.05 3762.4,1036.4 3764.05,1035.29 3766,1034.9 4029.9,1034.9 4029.9,195.1 3817.1,195.1 3817.1,763 3816.71,764.95 3815.6,766.6 3685.6,896.6 3683.95,897.71 3682,898.1 3217.1,898.1 3217.1,975 3216.71,976.95 3215.6,978.6 3213.95,979.71 3212,980.1 2580,980.1 2578.05,979.71 2576.4,978.6 2575.29,976.95 2574.9,975 2574.9,582.47 2329.28,582.47 2327.33,582.08 2325.67,580.98 2324.57,579.32 2324.18,577.37 2324.18,381.1 2234.37,381.1 2234.37,577.37 2233.99,579.32 2232.88,580.98 2231.23,582.08 2229.28,582.47 2229.27,582.47 1299.87,582.47 1299.87,1029.9 1646.9,1029.9 1646.9,652 1647.29,650.05 1648.4,648.4 1650.05,647.29 1652,646.9 1762,646.9 1763.95,647.29 1765.6,648.4 1766.71,650.05 1767.1,652 1767.1,1029.9 2571,1029.9 2572.95,1030.29 2574.6,1031.4 2575.71,1033.05 2576.1,1035 2576.1,1245 2575.71,1246.95 2574.6,1248.6 2572.95,1249.71 2571,1250.1 2007.1,1250.1 2007.1,1675 2006.71,1676.95 2005.6,1678.6 1972.1,1712.11 1972.1,1882.89 1999.11,1909.9 2989,1909.9 2990.95,1910.29 2992.6,1911.4 3016.11,1934.9 3433,1934.9 3434.95,1935.29 3436.6,1936.4 3437.71,1938.05 3438.1,1940 3438.1,1984.9 3760.9,1984.9
GND on Gnd-Plane - L7 (split plane): 6280.9,20.1 20.1,20.1 20.1,2659.9 6280.9,2659.9
GND on Gnd-Plane - L9 (split plane): 6280.9,20.1 20.1,20.1 20.1,2659.9 6280.9,2659.9

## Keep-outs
Keep-Out Layer:
  text ".Layer_Name" at 577,-858.49 h60

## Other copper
Top Layer - L1:
  text ".Layer_Name" at 577,-858.49 h60
Signals - L3:
  text ".Layer_Name" at 577,-858.49 h60
Signals - L6:
  text ".Layer_Name" at 577,-858.49 h60
Signals - L8:
  text ".Layer_Name" at 577,-858.49 h60
Bottom Layer - L10:
  text ".Layer_Name" at 577,-858.49 h60
Gnd-Plane - L9 (plane layer: these items are gaps in the copper):
  lines w21.46: 868.88,1315.42 898.34,1344.89 ; 868.88,1344.89 898.34,1315.42
  text ".Layer_Name" at 577,-858.49 h60
Gnd-Plane - L7 (plane layer: these items are gaps in the copper):
  lines w21.46: 868.88,1315.42 898.34,1344.89 ; 868.88,1344.89 898.34,1315.42
  text ".Layer_Name" at 577,-858.49 h60
Gnd-Plane - L4 (plane layer: these items are gaps in the copper):
  lines w21.46: 868.88,1315.42 898.34,1344.89 ; 868.88,1344.89 898.34,1315.42
  text ".Layer_Name" at 577,-858.49 h60
  text ".Layer_Name" at 577,-858.49 h60
Gnd-Plane - L2 (plane layer: these items are gaps in the copper):
  lines w10: 0,530 406,530 406,642 495,731 607,731 900,438 2915,438 2915,262 2979,198 3120,198 3243,75 3637,75 3727,165 3727,302 3812,387 3812,763 3682,893 3212,893 3212,975 2915,975 2915,577.37 879.26,577.37 643.63,813 438,813 406,845 406,1035 0,1035
  lines w21.46: 868.88,1315.42 898.34,1344.89 ; 868.88,1344.89 898.34,1315.42
  text ".Layer_Name" at 577,-858.49 h60
Pwr Plane - L5 (plane layer: these items are gaps in the copper):
  lines w10: 0,1035 406,1035 406,845 438,813 643.63,813 879.26,577.37 2229.28,577.37 2229.28,376 2329.28,376 2329.28,577.37 2580,577.37 2580,975 3212,975 3212,893 3682,893 3812,763 3812,190 5258,190 5258,0 ; 0,1600 254,1600 254,2025 861,2025 861,1483 1017.79,1483 1017.79,1035 1652,1035 ; 1294.78,577.37 1294.78,1035 ; 3347,2680 3347,2081 1677.04,2081 1587,1990.96 1587,1844.89 1652,1779.89 1652,652 1762,652 1762,1035 2571,1035 2571,1245 2002,1245 2002,1675 1967,1710 1967,1885 1997,1915 2989,1915 3014,1940 3433,1940 3433,1990 3766,1990 3766,1040 3950,1040 ; 3533,1990 3533,2680 ; 3950,2680 3950,1040 ; 4035,190 4035,1040 3950,1040 ; 4207,2680 4207,1990 4688,1990 ; 4904,1990 6301,1990 ; 5358,0 5358,565 6106,565 6106,665 6301,665 ; 2217,1558 2217,1712.27 2403,1712.27 2403,1865 2484,1865 2484,1840 3612.55,1840 3612.55,1740 3655.55,1740 3655.55,1463 3503,1463 3503,1376 3424,1376 3424,1415 2940,1415 2842,1513 2277,1513 2277,1558 2217,1558 ; 4688,1040 5116,1040 5116,1184 4904,1184 4904,2419 4688,2419 4688,1040
  text ".Layer_Name" at 577,-858.49 h60

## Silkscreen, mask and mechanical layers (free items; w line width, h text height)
Top Overlay:
  region: 2933,257 2633,257 2633,157 2933,157
  text ".PCB_Rev" at 5921,1225 h60 r90
  text ".PRJ_Title" at 5931,511 h60 r90
  text "TSW12J34EVM" at 6086,190 h60 r90
  text "TSW12J54EVM" at 6236,190 h60 r90
  text ".PRJ_Number" at 2025,177.01 h60
  text ".PCB_Rev" at 2475,177.01 h60
  text "-" at 2563,177.01 h60
  text ".Layer_Name" at 577,-858.49 h60
Bottom Overlay:
  text "CAUTION HOT SURFACE" at 3165,1322 h40
  text ".Layer_Name" at 577,-858.49 h60
Top Paste:
  text ".Layer_Name" at 577,-858.49 h60
Bottom Paste:
  text ".Layer_Name" at 577,-858.49 h60
Top Solder:
  text ".Layer_Name" at 577,-858.49 h60
  text ".Layer_Name" at 577,-858.49 h60
Bottom Solder:
  lines w12: 651.34,1269.98 678,1243.31 ; 651.34,1390.34 678,1417 ; 725.62,1308.63 745.33,1308.63 758.25,1295.71 ; 725.62,1351.69 745.33,1351.69 758.25,1364.61 ; 758.25,1297.24 781.33,1320.31 838.33,1320.31 ; 758.25,1363.08 781.33,1340 838.33,1340 ; 1024.47,1311.47 1061.96,1273.97 ; 1024.47,1348.85 1061.96,1386.34 ; 1334.32,1312.84 1343.63,1322.16 1464.32,1322.16 1476,1310.47 1487.69,1322.16 1530.63,1322.16 1532.47,1320.32 ; 1334.32,1347.47 1343.63,1338.16 1464.31,1338.16 1476,1349.84 1487.68,1338.16 1530.63,1338.16 1532.47,1340
  lines w14: 648,1269.98 651.34,1269.98 ; 648,1390.34 651.34,1390.34 ; 678,1243.31 680.41,1243.31 680.41,1026.53 ; 678,1417 680.41,1417 680.41,1633.79 ; 680.41,1278.16 680.41,1312.81 ; 680.41,1347.5 680.41,1382.16 ; 719.78,1314.47 725.62,1308.63 ; 719.78,1345.84 725.62,1351.69 ; 758.25,1295.71 758.25,1297.24 ; 758.25,1363.08 758.25,1364.61 ; 928.89,1320.31 979.26,1320.31 985.1,1314.47 ; 928.89,1340 979.26,1340 985.1,1345.84 ; 1024.47,1311.47 1024.47,1314.47 ; 1024.47,1345.84 1024.47,1348.85 ; 1061.97,1273.97 1096.24,1273.97 ; 1061.97,1386.34 1096.24,1386.34 ; 1146.64,1273.97 1179.1,1273.97 1211.55,1273.97 ; 1146.64,1386.34 1211.55,1386.34 ; 1261.95,1273.97 1261.95,1281.95 1292.84,1312.84 1294.95,1312.84 ; 1261.95,1386.34 1261.95,1378.37 1292.84,1347.47 1294.95,1347.47
  text ".Layer_Name" at 577,-858.49 h60
Drill Guide:
  text ".Layer_Name" at 577,-858.49 h60
M1 Board Outline:
  the board outline again, w10
  text ".Layer_Name" at 577,-858.49 h60
M2 Board Dimensions:
  rectangle: -0.5,-285.5 124.5,-160.5
  rectangle: 124.5,-410.5 499.5,-285.5
  lines w7: -0.5,-285.5 999.5,-285.5 ; 124.5,-410.5 124.5,-160.5 ; 249.5,-410.5 249.5,-160.5 ; 499.5,-410.5 499.5,-160.5 ; 749.5,-410.5 749.5,-160.5 ; -0.5,-410.5 999.5,-410.5 999.5,-160.5 -0.5,-160.5 -0.5,-410.5
  lines w10: -0.5,-475.5 -0.5,-455.5 ; 59.5,-485.5 -0.5,-465.5 ; 59.5,-445.5 -0.5,-465.5 ; 223.58,-465.5 -0.5,-465.5 ; 775.42,-465.5 999.5,-465.5 ; 939.5,-485.5 999.5,-465.5 ; 939.5,-445.5 999.5,-465.5 ; 999.5,-475.5 999.5,-455.5
  text "1000 (mil)" at 233.58,-501.49 h60
  text ".Layer_Name" at 577,-858.49 h60
M3 3D STEP Top:
  text ".Layer_Name" at 577,-858.49 h60
M4 3D STEP Bottom:
  text ".Layer_Name" at 577,-858.49 h60
M5 Assembly Top:
  lines w7: 6793,-129.5 7918,-129.5 ; 6793,-9.5 7918,-9.5 ; 6793,110.5 7918,110.5 ; 6793,233 7915.5,233 ; 7108,-249.5 7108,353 ; 6793,-249.5 7918,-249.5 7918,353 6793,353 6793,-249.5
  lines w10: -292,-930.17 6308,-930.17 ; -292,-726.83 6310,-726.83 ; -292,-523.5 -292,-1133.5 3713,-1133.5 6310,-1133.5 6310,-523.5 -291.5,-523.5 -291.5,-1133.5 1284,-1133.5 ; 2173,-1133.5 2173,-523.5 ; 3440,-726.83 3440,-523.5 ; 4280,-726.83 4280,-523.5 ; 4902,-1140 4902,-937.17
  text "TABLE 1" at 7180.5,388 h40
  text "Variant" at 6818,278 h40
  text "Box To Check" at 7253,278 h40
  text "001" at 6885.5,158 h40
  text "TSW12J54EVM" at 7272.99,155.5 h40
  text "002" at 6885.5,33 h40
  text "TSW12J34EVM" at 7267.99,30.5 h40
  text "COMPONENTS MARKED 'DNP' SHOULD NOT BE POPULATED, AND MAY NOT BE IN BILL OF MATERIALS" at 1153.5,-318.5 h60
  text "ASSEMBLY VARIANT:" at 1153,-434 h60
  text ".VariantName" at 2189,-434 h60
  text "PCB VIEWED FROM TOP SIDE" at -228.5,-655.67 h60
  text "BOARD #:" at 2248,-655.67 h60
  text ".PRJ_Number" at 2793.5,-655.67 h60
  text "REV:" at 3638,-655.67 h60
  text ".PCB_Rev" at 3929.5,-655.67 h60
  text "SVN REV:" at 4476,-655.67 h60
  text ".VersionControl_RevNumber" at 4982,-655.67 h60
  text "IGNORE ->" at -228.5,-858.49 h60
  text "PLOT NAME =" at -228.5,-1064.34 h60
  text ".plot_File_Name" at 577,-1064.34 h60
  text "GENERATED    :" at 2250,-1064.34 h60
  text ".Print_Date" at 3119.5,-1064.34 h60
  text ".Print_Time" at 3848.5,-1064.34 h60
  text "TEXAS INSTRUMENTS" at 5113,-1064.34 h60
M6 Assembly Bottom:
  lines w10: -292.5,-727.33 6309.5,-727.33 ; -290.5,-930.67 6309.5,-930.67 ; 1115.5,-1140.5 1115.5,-937.67 ; 1737.5,-727.33 1737.5,-524 ; 2577.5,-727.33 2577.5,-524 ; 3844.5,-1134 3844.5,-524 ; 4733.5,-1134 6309,-1134 6309,-524 -292.5,-524 -292.5,-1134 2304.5,-1134 6309.5,-1134 6309.5,-524
  text "COMPONENTS MARKED 'DNP' SHOULD NOT BE POPULATED, AND MAY NOT BE IN BILL OF MATERIALS" at 6102,-318 h60
  text ".VariantName" at 5058,-434 h60
  text "ASSEMBLY VARIANT:" at 6097,-434 h60
  text ".VersionControl_RevNumber" at 1035.5,-656.17 h60
  text "SVN REV:" at 1541.5,-656.17 h60
  text ".PCB_Rev" at 2088,-656.17 h60
  text "REV:" at 2379.5,-656.17 h60
  text ".PRJ_Number" at 3224,-656.17 h60
  text "BOARD #:" at 3769.5,-656.17 h60
  text "PCB VIEWED FROM BOTTOM SIDE" at 6246,-656.17 h60
  text "IGNORE ->" at 2547.85,-858.49 h60
  text "TEXAS INSTRUMENTS" at 904.5,-1064.84 h60
  text ".Print_Time" at 2169,-1064.84 h60
  text ".Print_Date" at 2898,-1064.84 h60
  text "GENERATED    :" at 3767.5,-1064.84 h60
  text ".plot_File_Name" at 5440.5,-1064.84 h60
  text "PLOT NAME =" at 6246,-1064.84 h60
M9 Title Sheet:
  drawing of 57 lines, arcs and shapes, not listed
  text "1" at 739.84,8036.5 h70
  text "2" at 3235.5,8036.5 h70
  text "3" at 5724.84,8036.5 h70
  text "4" at 8231.51,8036.5 h70
  text "5" at 10730.5,8036.5 h70
  text "6" at 13235.5,8036.5 h70
  text "A" at -416.5,6893.5 h70
  text "A" at 14383.5,6893.5 h70
  text "B" at -416.5,4513.5 h70
  text "B" at 14383.5,4513.5 h70
  text "C" at -416.5,2138.5 h70
  text "C" at 14383.5,2138.5 h70
  text "PROJECT TITLE:" at 11343.5,277.5 h45
  text ".PRJ_Title" at 11393.5,144.17 h70
  text "DESIGNED FOR:" at 11343.5,-23.5 h45
  text ".PRJ_Customer" at 11393.5,-163.5 h70
  text "D" at -416.5,-231.5 h70
  text "D" at 14383.5,-231.5 h70
  text "FILE NAME:" at 11343.5,-323.5 h45
  text ".PCB_File_Name_No_Path" at 11393.5,-443.5 h70
  text "Texas Instruments (TI) and/or its licensors do not warrant the accuracy or completeness of this specification" at 6374,-605.34 h45
  text "ENGINEER:" at 11343.5,-613.5 h45
  text "LAYOUT BY:" at 12848.5,-613.5 h45
  text "or any information contained therein. TI and/or its licensors do not warrant that this design will meet" at 6329.01,-718 h45
  text ".PRJ_Engineer" at 11393.5,-768.49 h70
  text ".PCB_Layout" at 12899,-768.49 h70
  text "the specifications, will be suitable for your application or fit for any particular purpose, or will operate in" at 6329.01,-830.67 h45
  text ".Layer_Name" at 577,-858.49 h60
  text "ALTIUM DESIGNER VERSION:" at 12848.5,-923.5 h45
  text "an implementation. TI and/or its licensors do not warrant that the design is production worthy. You should" at 6329.01,-943.33 h45
  text "completely validate and test your design implementation to confirm the system functionality for your application." at 6374,-1056 h45
  text ".print_Scale" at 11393.5,-1056.83 h70
  text ".Application_BuildNumber" at 12899,-1056.83 h70
  text "1" at 739.84,-1263.5 h70
  text "2" at 3235.5,-1263.5 h70
  text "3" at 5724.84,-1263.5 h70
  text "4" at 8231.51,-1263.5 h70
  text "5" at 10730.5,-1263.5 h70
  text "6" at 13235.5,-1263.5 h70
